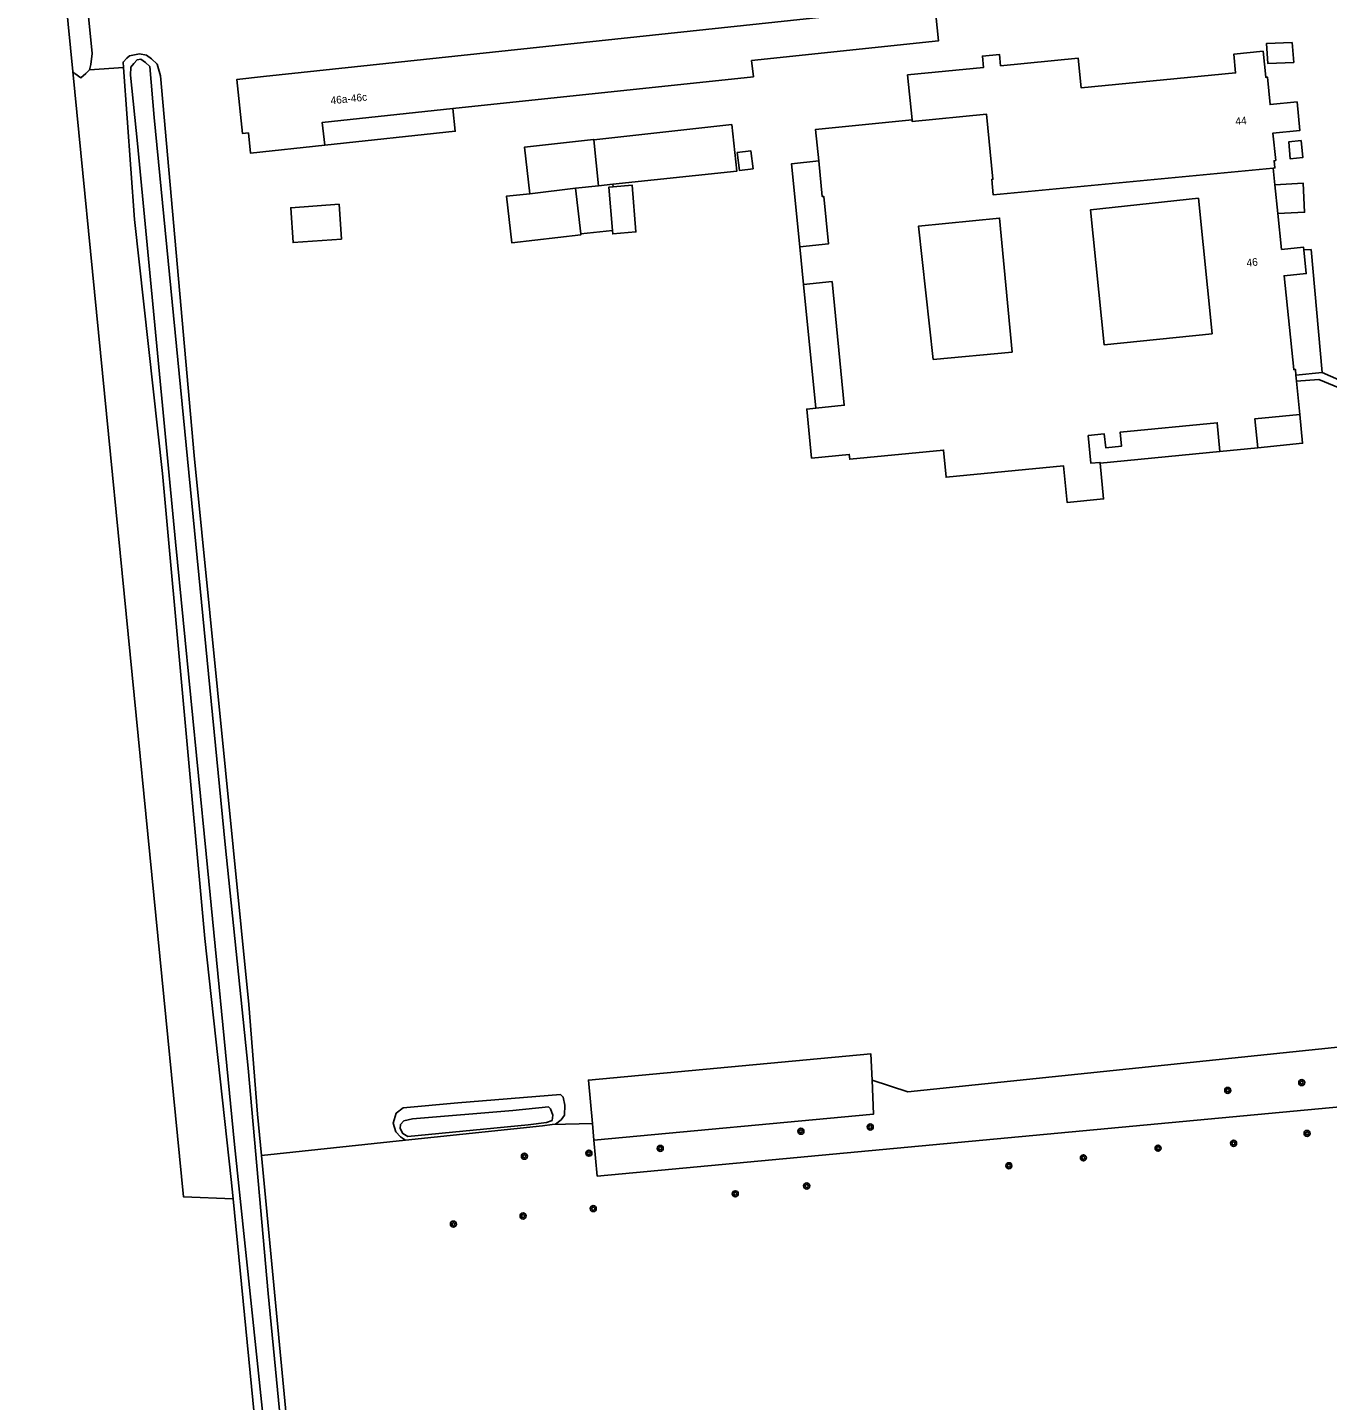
# Model space of a CAD drawing. Extents: x 140000 to 143000, y 403500 to 406000.
# Drawn here: x 140352.4 to 140523.7, y 403984.8 to 404165.7 of the extents above; entities that cross this region are included whole.
import ezdxf

# ---------------------------------------------------------------- set-up
doc = ezdxf.new("R2010")
doc.units = 0
for name, color, linetype in [('gg-afsc-erfafscheiding', 7, 'Continuous'), ('gg-anno-huisnummerreeks BGT', 7, 'Continuous'), ('gg-bbg-bijgebouw', 7, 'Continuous'), ('gg-bbg-hoofdgebouw', 7, 'Continuous'), ('gg-bbg-luifel en loopbrug', 7, 'Continuous'), ('gg-bbg-tussenscheiding', 7, 'Continuous'), ('gg-knt-verharding', 7, 'Continuous'), ('gg-knt-verharding nz', 7, 'Continuous'), ('gg-kntw-bovenkant insteek waterloop', 7, 'Continuous'), ('gg-kntw-waterlijn', 7, 'Continuous'), ('gt-grn-groengrens', 7, 'Continuous'), ('gt-symb-boom', 7, 'Continuous')]:
    doc.layers.add(name, color=color, linetype=linetype)

# ---------------------------------------------------------------- blocks, each defined once
blk = doc.blocks.new('gt0-BOOM')
at = {"layer": 'gt-symb-boom'}
for radius in [0.4, 0.2]:
    blk.add_circle((0, 0), radius, dxfattribs=at)

msp = doc.modelspace()

# ---------------------------------------------------------------- linework, layer by layer
at = {"layer": 'gg-afsc-erfafscheiding'}
msp.add_line((140402.21, 404019.11), (140383.25, 404017.1), dxfattribs=at)
for points in [[(140519.05, 404163.71), (140515.67, 404163.56), (140515.87, 404160.93), (140519.27, 404161.08), (140519.05, 404163.71)], [(140517.18, 404141.19), (140520.69, 404141.35), (140520.51, 404145.19), (140516.79, 404144.94)], [(140519.64, 404119.08), (140522.58, 404119.33), (140532.22, 404115.31), (140542.93, 404111.61)]]:
    msp.add_lwpolyline(points, dxfattribs=at)
at = {"layer": 'gg-bbg-bijgebouw'}
for p, q in [((140427.66, 404144.84), (140427.03, 404150.89)), ((140424.63, 404144.53), (140427.66, 404144.84)), ((140425.32, 404138.5), (140424.63, 404144.53))]:
    msp.add_line(p, q, dxfattribs=at)
for points in [[(140427.03, 404150.89), (140427.02, 404150.95), (140417.92, 404149.93), (140418.61, 404143.79)], [(140429.49, 404138.93), (140429.04, 404144.66), (140429.57, 404144.7)], [(140429.49, 404138.93), (140429.53, 404138.49), (140432.59, 404138.75), (140432.11, 404144.9), (140429.57, 404144.7)], [(140418.61, 404143.79), (140415.53, 404143.45), (140416.22, 404137.32), (140425.34, 404138.38), (140425.32, 404138.5)], [(140393.8, 404137.81), (140387.42, 404137.36), (140387.1, 404141.95), (140393.48, 404142.4), (140393.8, 404137.81)]]:
    msp.add_lwpolyline(points, dxfattribs=at)
at = {"layer": 'gg-bbg-hoofdgebouw'}
for p, q in [((140516.79, 404144.94), (140516.56, 404147.17)), ((140517.18, 404141.19), (140516.79, 404144.94)), ((140454.19, 404136.8), (140454.68, 404131.83)), ((140519.64, 404119.08), (140519.56, 404119.91)), ((140520.07, 404114.7), (140519.64, 404119.08)), ((140509.55, 404109.84), (140514.52, 404110.33))]:
    msp.add_line(p, q, dxfattribs=at)
for points in [[(140408.46, 404155), (140448.06, 404159.2), (140447.84, 404161.32), (140472.46, 404163.93), (140471.96, 404168.62), (140383.5, 404159.22), (140380.01, 404158.85), (140380.76, 404151.71), (140381.52, 404151.79), (140381.8, 404149.15), (140391.58, 404150.18)], [(140516.56, 404147.17), (140516.78, 404147.19), (140516.69, 404148.14), (140516.9, 404148.18), (140516.53, 404151.78), (140520.08, 404152.12), (140519.7, 404155.89), (140516.16, 404155.54), (140515.8, 404159.15), (140515.58, 404159.14), (140515.23, 404162.56), (140511.36, 404162.16), (140511.6, 404159.69), (140491.26, 404157.72), (140490.88, 404161.64), (140480.64, 404160.64), (140480.49, 404162.14), (140478.24, 404161.92), (140478.39, 404160.42), (140468.39, 404159.43), (140468.98, 404153.51)], [(140408.46, 404155), (140391.26, 404153.18), (140391.58, 404150.18)], [(140468.98, 404153.51), (140456.26, 404152.25), (140456.67, 404148.1)], [(140456.67, 404148.1), (140457.13, 404143.41), (140457.34, 404143.43), (140457.96, 404137.17), (140454.19, 404136.8)], [(140508.5, 404125.32), (140494.28, 404123.89), (140492.49, 404141.67), (140506.7, 404143.19), (140508.5, 404125.32)], [(140520.6, 404136.4), (140520.57, 404136.73), (140517.67, 404136.45), (140517.18, 404141.19)], [(140482.18, 404122.92), (140471.76, 404121.96), (140469.84, 404139.52), (140480.5, 404140.59), (140482.18, 404122.92)], [(140520.6, 404136.4), (140520.91, 404133.27), (140518, 404132.99), (140519.27, 404120.63), (140519.49, 404120.65), (140519.56, 404119.91)], [(140454.68, 404131.83), (140458.44, 404132.21), (140460.05, 404115.92), (140456.3, 404115.55)], [(140456.3, 404115.55), (140455.1, 404115.43), (140455.74, 404108.96), (140460.7, 404109.45), (140460.77, 404108.81), (140473.12, 404110.03), (140473.46, 404106.45), (140488.94, 404107.93), (140489.41, 404103.12), (140494.21, 404103.58), (140493.75, 404108.28)], [(140514.52, 404110.33), (140514.14, 404114.12), (140520.07, 404114.7)], [(140493.75, 404108.28), (140493.74, 404108.39), (140492.55, 404108.28), (140492.19, 404111.93), (140494.31, 404112.15), (140494.49, 404110.33), (140496.56, 404110.53), (140496.38, 404112.36), (140509.18, 404113.63), (140509.55, 404109.84)]]:
    msp.add_lwpolyline(points, dxfattribs=at)
at = {"layer": 'gg-bbg-luifel en loopbrug'}
for p, q in [((140429.53, 404145.04), (140427.66, 404144.84)), ((140429.53, 404145.04), (140429.57, 404144.7)), ((140429.49, 404138.93), (140425.32, 404138.5)), ((140454.68, 404131.83), (140456.3, 404115.55)), ((140493.75, 404108.28), (140509.55, 404109.84))]:
    msp.add_line(p, q, dxfattribs=at)
for points in [[(140408.46, 404155), (140408.78, 404152.01), (140391.58, 404150.18)], [(140427.03, 404150.89), (140445.22, 404152.89), (140445.9, 404146.76), (140429.53, 404145.04)], [(140448.03, 404147.07), (140447.71, 404149.45), (140445.93, 404149.21), (140446.24, 404146.83), (140448.03, 404147.07)], [(140456.67, 404148.1), (140453.11, 404147.74), (140454.19, 404136.8)], [(140514.52, 404110.33), (140520.44, 404110.92), (140520.07, 404114.7)]]:
    msp.add_lwpolyline(points, dxfattribs=at)
at = {"layer": 'gg-bbg-tussenscheiding'}
msp.add_line((140418.61, 404143.79), (140424.63, 404144.53), dxfattribs=at)
msp.add_lwpolyline([(140516.56, 404147.17), (140479.68, 404143.64), (140479.47, 404145.68), (140479.64, 404145.69), (140478.78, 404154.28), (140469, 404153.3), (140468.98, 404153.51)], dxfattribs=at)
at = {"layer": 'gg-knt-verharding'}
for p, q in [((140360.57, 404160.11), (140365.07, 404160.42)), ((140523.01, 404120.22), (140532.67, 404115.99)), ((140421.53, 404021.18), (140426.86, 404021.31)), ((140426.86, 404021.31), (140427.06, 404019.11))]:
    msp.add_line(p, q, dxfattribs=at)
for points in [[(140520.27, 404150.78), (140520.45, 404148.55), (140518.81, 404148.38), (140518.63, 404150.64), (140520.27, 404150.78)], [(140520.6, 404136.4), (140521.56, 404136.43), (140523.01, 404120.22)], [(140538.19, 404032.74), (140539.02, 404024.78), (140427.5, 404014.39), (140427.06, 404019.11)], [(140463.7, 404027.03), (140468.4, 404025.5), (140538.19, 404032.74)], [(140426.86, 404021.31), (140426.32, 404027.03), (140463.54, 404030.5), (140463.7, 404027.03)]]:
    msp.add_lwpolyline(points, dxfattribs=at)
at = {"layer": 'gg-knt-verharding nz'}
msp.add_lwpolyline([(140463.7, 404027.03), (140463.9, 404022.55), (140427.06, 404019.11)], dxfattribs=at)
at = {"layer": 'gg-kntw-bovenkant insteek waterloop'}
for points in [[(140360.57, 404160.11), (140360.78, 404160.83), (140360.93, 404162.26), (140356.38, 404208.22), (140355.1, 404220.63), (140354.53, 404221.22), (140353.82, 404221.3), (140353.28, 404221.14), (140352.72, 404220.55)], [(140352.72, 404220.55), (140352.51, 404219.76), (140352.41, 404218.87), (140352.75, 404216.92), (140358.37, 404159.87)], [(140383.25, 404017.1), (140382.73, 404022.53), (140381.56, 404037.01), (140374.38, 404109.31), (140369.94, 404159.3), (140369.51, 404160.86), (140368.74, 404161.57), (140368.1, 404162.03), (140367.18, 404162.21), (140365.86, 404161.96), (140365.49, 404161.63), (140365.02, 404161.12), (140365.07, 404160.42)], [(140360.57, 404160.11), (140360.11, 404159.62), (140359.45, 404159.06), (140358.65, 404159.61), (140358.37, 404159.87)], [(140365.07, 404160.42), (140366.51, 404140.39), (140370.2, 404106.92), (140375.8, 404045.7), (140379.25, 404013.94), (140379.51, 404011.38)], [(140421.53, 404021.18), (140421.98, 404021.24), (140422.72, 404021.82), (140423.16, 404022.43), (140423.22, 404023.73), (140423.01, 404024.81), (140422.64, 404025.15), (140409.1, 404024.04), (140401.92, 404023.37), (140401, 404022.68), (140400.59, 404021.37), (140400.94, 404020.22), (140401.56, 404019.58), (140402.21, 404019.11)], [(140421.53, 404021.18), (140420.27, 404021), (140402.21, 404019.11)], [(140383.39, 403969.57), (140383.74, 403968.5), (140384.11, 403967.95), (140384.58, 403967.52), (140385.15, 403967.33), (140386.16, 403967.54), (140387.08, 403968.16), (140387.62, 403968.95), (140387.77, 403969.55), (140383.25, 404017.1)], [(140379.51, 404011.38), (140382.68, 403979.03), (140383.39, 403969.57)]]:
    msp.add_lwpolyline(points, dxfattribs=at)
at = {"layer": 'gg-kntw-waterlijn'}
for points in [[(140371.91, 404097.95), (140366.93, 404150.41), (140365.99, 404159.4), (140366.02, 404160.46), (140366.42, 404160.96), (140366.86, 404161.43), (140367.35, 404161.52), (140367.96, 404161.08), (140368.54, 404160.54), (140369.12, 404153.84), (140378.48, 404058.08), (140381.51, 404028.61), (140384.12, 403998.92), (140386.61, 403973.54), (140386.92, 403969.8), (140386.55, 403969.26), (140386.04, 403968.79), (140385.52, 403968.81), (140385.12, 403969.04), (140384.83, 403969.59), (140379.69, 404018.54), (140375.97, 404056.84), (140371.91, 404097.95)], [(140421.35, 404023.26), (140421.66, 404022.43), (140421.54, 404021.72), (140420.82, 404021.45), (140418.38, 404021.16), (140402.54, 404019.62), (140401.87, 404019.99), (140401.53, 404020.64), (140401.58, 404021.2), (140402.02, 404021.67), (140403.13, 404021.92), (140416.35, 404023.05), (140421.06, 404023.53), (140421.35, 404023.26)]]:
    msp.add_lwpolyline(points, dxfattribs=at)
at = {"layer": 'gt-grn-groengrens'}
msp.add_line((140519.56, 404119.91), (140523.01, 404120.22), dxfattribs=at)
msp.add_lwpolyline([(140358.37, 404159.87), (140372.98, 404011.66), (140379.51, 404011.38)], dxfattribs=at)

# ---------------------------------------------------------------- block references
at = {"layer": 'gt-symb-boom'}
for p in [(140520.32, 404026.71), (140510.58, 404025.68), (140454.33, 404020.3), (140463.46, 404020.86), (140521.03, 404020.01), (140435.79, 404018.04), (140501.4, 404018.07), (140511.34, 404018.71), (140417.89, 404017.01), (140426.39, 404017.41), (140491.55, 404016.8), (140481.73, 404015.76), (140455.09, 404013.09), (140445.68, 404012.06), (140417.72, 404009.14), (140426.97, 404010.11), (140408.54, 404008.07)]:
    msp.add_blockref('gt0-BOOM', p, dxfattribs=at)

# ---------------------------------------------------------------- texts
at = {"layer": 'gg-anno-huisnummerreeks BGT'}
for s, rotation, p in [('46a-46c', 6, (140392.4, 404155.56)), ('44', 5.7, (140511.63, 404152.82)), ('46', 5.9, (140513.1, 404134.18))]:
    msp.add_text(s, height=1, rotation=rotation, dxfattribs=at).set_placement(p)

doc.saveas('drawing.dxf')
